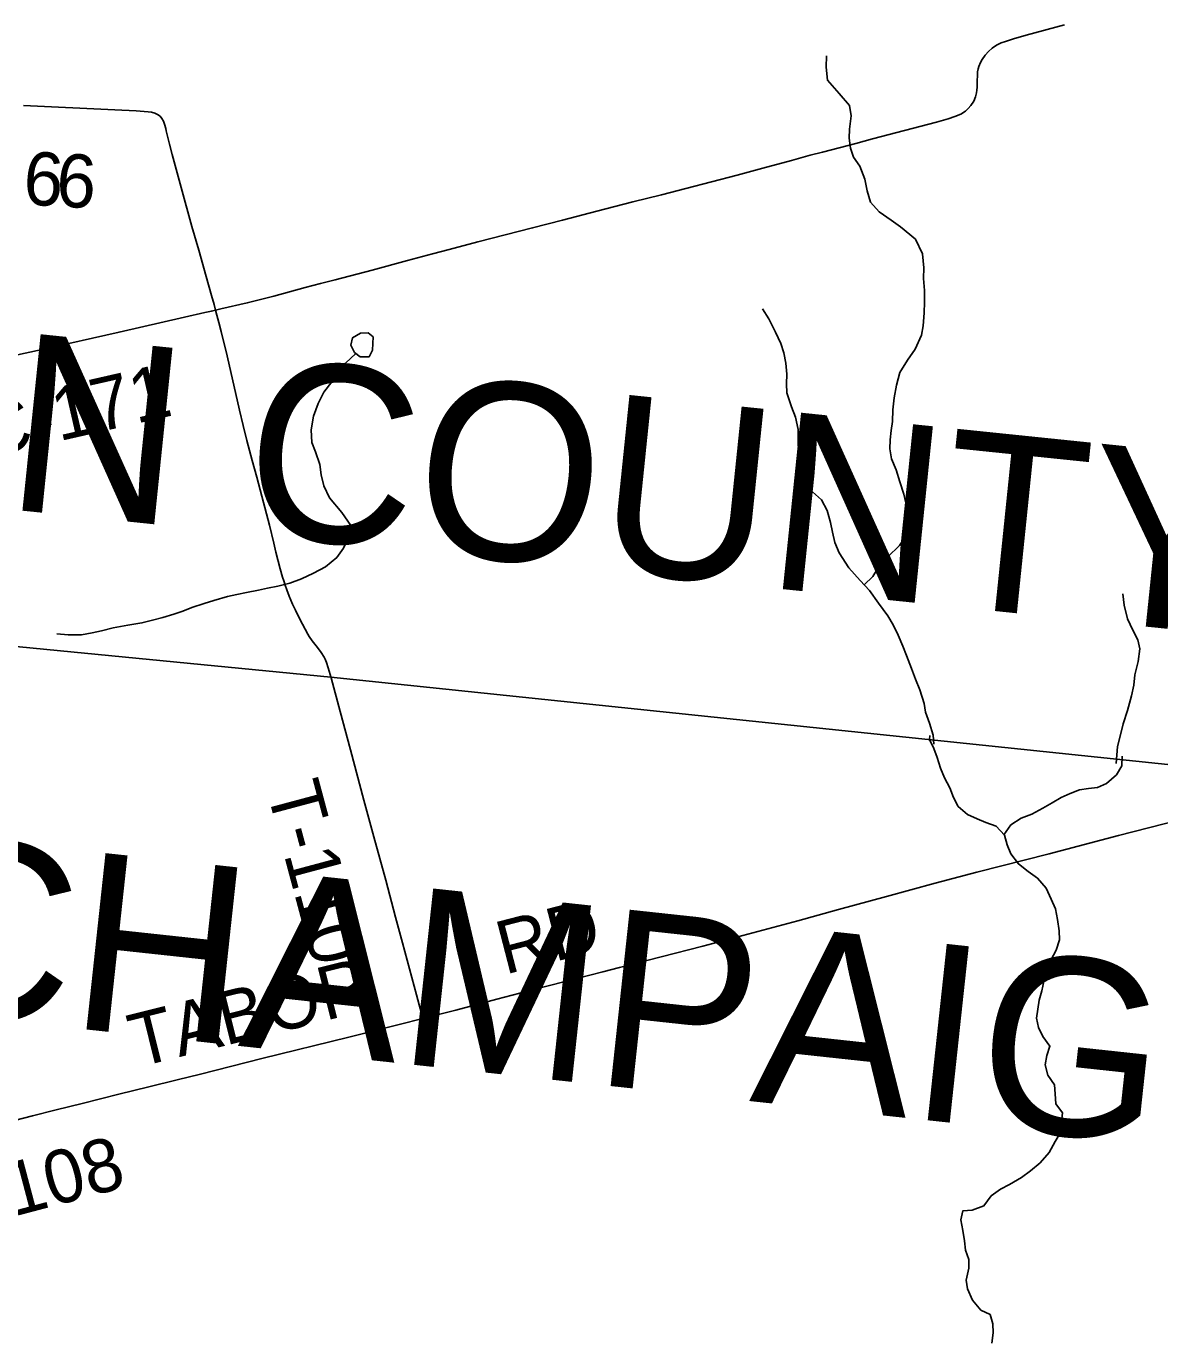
# Model space of a CAD drawing. Extents: x 0 to 1101, y 0 to 440.
# Drawn here: x 844.169 to 845.379, y 375.861 to 377.265 of the extents above; entities that cross this region are included whole.
import ezdxf

# ---------------------------------------------------------------- set-up
doc = ezdxf.new("R2010")
doc.units = 0
for name, color, linetype in [('GM_X_County_Road', 7, 'Continuous'), ('GM_X_County_Road_Text', 7, 'Continuous'), ('GM_X_County_Text', 7, 'Continuous'), ('GM_X_Minor_Lake', 7, 'Continuous'), ('GM_X_Minor_River', 7, 'Continuous'), ('GM_X_Township', 7, 'Continuous'), ('GM_X_Township_Road', 7, 'Continuous'), ('GM_X_Township_Road_Text', 7, 'Continuous'), ('SH_Cut_Line', 7, 'Continuous')]:
    doc.layers.add(name, color=color, linetype=linetype)

msp = doc.modelspace()

# ---------------------------------------------------------------- linework, layer by layer
at = {"layer": 'GM_X_County_Road'}
for points in [[(843.7743, 376.6401), (844.4941, 376.5699), (845.4182, 376.4736), (845.5612, 376.461), (845.6523, 376.4464), (845.8289, 376.4273), (846.6778, 376.3437), (847.4662, 376.2566), (847.5303, 377.0082), (847.5335, 377.0456), (847.6089, 377.9284)], [(844.1415, 376.9102), (844.186, 376.9197), (844.268, 376.9384), (844.3378, 376.9543), (844.3595, 376.9592), (844.3666, 376.9608), (844.371, 376.9617), (844.3766, 376.9631), (844.4048, 376.9696), (844.4333, 376.9766), (844.4668, 376.9859), (844.483, 376.9902), (844.4986, 376.9942), (844.5382, 377.0046), (844.576, 377.0148), (844.6024, 377.0219), (844.6204, 377.0267), (844.651, 377.0347), (844.7094, 377.0496), (844.7413, 377.0579), (844.7779, 377.0674), (844.8164, 377.0774), (844.8471, 377.0851), (844.873, 377.0917), (844.9278, 377.1058), (844.9553, 377.1133), (844.9859, 377.1217), (845.0056, 377.1272), (845.0188, 377.1306), (845.0544, 377.1399), (845.0722, 377.1449), (845.1405, 377.1627), (845.1531, 377.166), (845.1602, 377.1685), (845.1664, 377.1712), (845.1714, 377.1742), (845.1743, 377.177), (845.1774, 377.1802), (845.1805, 377.1851), (845.1822, 377.1896), (845.1834, 377.1938), (845.1838, 377.1966), (845.1839, 377.1999), (845.1841, 377.2041), (845.1839, 377.2073), (845.1842, 377.2116), (845.1845, 377.2161), (845.1851, 377.2194), (845.1859, 377.2221), (845.1874, 377.2262), (845.1893, 377.2294), (845.1924, 377.2339), (845.196, 377.238), (845.2001, 377.2416), (845.2046, 377.2447), (845.2095, 377.2473), (845.2144, 377.2488), (845.2227, 377.2514), (845.2363, 377.2555), (845.2772, 377.2665)], [(844.5922, 376.2055), (844.6274, 376.2145), (844.6713, 376.2262), (844.7122, 376.2368), (844.7428, 376.2448), (844.7843, 376.2555), (844.8023, 376.2601), (844.8911, 376.2827), (844.9924, 376.31), (845.036, 376.3221), (845.0871, 376.3359), (845.1392, 376.3502), (845.1835, 376.3617), (845.2609, 376.3815), (845.335, 376.4008), (845.3837, 376.4134), (845.4274, 376.4244)], [(844.0063, 376.0564), (844.0507, 376.0684), (844.1098, 376.0843), (844.1565, 376.0968), (844.1757, 376.1016), (844.201, 376.108), (844.2287, 376.115), (844.2679, 376.1247), (844.2999, 376.1326), (844.33, 376.14), (844.3548, 376.1462), (844.4204, 376.1628), (844.5133, 376.1858), (844.5669, 376.1991), (844.5922, 376.2055)]]:
    msp.add_lwpolyline(points, dxfattribs=at)
at = {"layer": 'GM_X_Minor_Lake'}
for points in [[(844.5253, 376.9121), (844.5348, 376.9119), (844.5384, 376.9191), (844.5394, 376.9332), (844.5338, 376.9375), (844.5258, 376.9372), (844.5173, 376.9324), (844.5153, 376.9244), (844.5193, 376.9167)], [(844.5193, 376.9167), (844.5253, 376.9121)]]:
    msp.add_lwpolyline(points, dxfattribs=at)
at = {"layer": 'GM_X_Minor_River'}
for points in [[(845.0635, 376.6685), (845.0728, 376.6775), (845.0787, 376.6874), (845.0885, 376.6986), (845.1012, 376.7106), (845.1099, 376.7238), (845.1102, 376.7394), (845.1089, 376.7516), (845.1057, 376.7654), (845.1014, 376.7784), (845.0975, 376.7914), (845.0924, 376.803), (845.0907, 376.8137), (845.0912, 376.8232), (845.0922, 376.8334), (845.0935, 376.8429), (845.0941, 376.8555), (845.0955, 376.8681), (845.098, 376.8817), (845.1013, 376.8954), (845.1096, 376.9086), (845.1178, 376.9202), (845.1246, 376.935), (845.1263, 376.9452), (845.1273, 376.9589), (845.1279, 376.9704), (845.1278, 376.9829), (845.1268, 376.9955), (845.1271, 377.007), (845.1255, 377.0219), (845.1181, 377.0376), (845.102, 377.0509), (845.0923, 377.0579), (845.0795, 377.0669), (845.0702, 377.077), (845.0666, 377.0892), (845.0642, 377.1018), (845.0588, 377.1157), (845.0521, 377.1253), (845.0489, 377.1349), (845.0472, 377.1456), (845.0477, 377.1551), (845.0495, 377.1692), (845.0478, 377.1803), (845.0366, 377.193), (845.0244, 377.2074), (845.0227, 377.2211), (845.023, 377.2333)], [(845.1379, 376.4985), (845.1369, 376.508), (845.133, 376.521), (845.129, 376.5325), (845.1273, 376.542), (845.1227, 376.5566), (845.1183, 376.5677), (845.114, 376.5793), (845.1085, 376.5931), (845.1045, 376.6031), (845.0998, 376.6149), (845.0943, 376.6257), (845.0888, 376.6353), (845.0788, 376.6489), (845.0691, 376.6624), (845.0591, 376.6732), (845.0471, 376.6868), (845.0368, 376.7026), (845.0321, 376.7137), (845.0296, 376.7248), (845.0275, 376.7351), (845.024, 376.7478), (845.0177, 376.7593), (845.005, 376.7706), (844.9991, 376.7814), (844.9941, 376.796), (844.9932, 376.8105), (844.993, 376.8223), (844.9929, 376.8345), (844.9901, 376.8475), (844.9857, 376.8586), (844.9807, 376.8736), (844.9805, 376.8831), (844.9807, 376.8934), (844.9798, 376.9052), (844.9777, 376.9163), (844.9745, 376.9263), (844.9686, 376.9382), (844.9617, 376.9524), (844.955, 376.9632)], [(844.2016, 376.6163), (844.2138, 376.6153), (844.2278, 376.6151), (844.2393, 376.6175), (844.2492, 376.6193), (844.2618, 376.6225), (844.2775, 376.6256), (844.2924, 376.628), (844.3038, 376.6309), (844.3146, 376.6338), (844.3264, 376.6374), (844.336, 376.6406), (844.3456, 376.6443), (844.359, 376.6486), (844.3693, 376.6519), (844.3838, 376.6562), (844.3938, 376.6583), (844.4041, 376.6604), (844.4167, 376.6628), (844.4266, 376.665), (844.4373, 376.6671), (844.4503, 376.6703), (844.4629, 376.675), (844.4756, 376.6809), (844.4883, 376.6879), (844.5003, 376.6976), (844.5077, 376.7078), (844.5133, 376.7198), (844.5154, 376.732), (844.5058, 376.7459), (844.4927, 376.7614), (844.4865, 376.7744), (844.4837, 376.7859), (844.4824, 376.797), (844.4777, 376.8104), (844.4737, 376.8204), (844.4732, 376.8341), (844.4754, 376.8485), (844.4806, 376.8622), (844.4865, 376.8743), (844.4951, 376.8852), (844.5025, 376.8953), (844.5096, 376.9051), (844.5208, 376.9156)], [(845.3324, 376.4779), (845.3338, 376.496), (845.3367, 376.507), (845.34, 376.5203), (845.3444, 376.5343), (845.3489, 376.5502), (845.3514, 376.5616), (845.3524, 376.5726), (845.3557, 376.5867), (845.3575, 376.6004), (845.3554, 376.6099), (845.3503, 376.6203), (845.3444, 376.6322), (845.3409, 376.6468), (845.3396, 376.659)], [(845.1638, 376.4319), (845.1586, 376.4415), (845.1549, 376.4518), (845.1492, 376.4626), (845.1448, 376.4729), (845.1414, 376.4844), (845.1377, 376.4939), (845.1332, 376.5035), (845.1333, 376.5077)], [(845.2126, 376.4018), (845.22, 376.4123), (845.2311, 376.4195), (845.2422, 376.4236), (845.254, 376.43), (845.264, 376.436), (845.2736, 376.4416), (845.2831, 376.4457), (845.2934, 376.4498), (845.303, 376.4512), (845.3125, 376.4523), (845.322, 376.4564), (845.3328, 376.4658), (845.3386, 376.4753), (845.3387, 376.4856)], [(845.1998, 375.859), (845.2011, 375.87), (845.2008, 375.8796), (845.1978, 375.8895), (845.188, 375.8942), (845.1789, 375.9049), (845.1737, 375.9168), (845.1723, 375.9263), (845.175, 375.9389), (845.1751, 375.9484), (845.1714, 375.9584), (845.1704, 375.9683), (845.1686, 375.9794), (845.1664, 375.9908), (845.1687, 376.0003), (845.1786, 376.001), (845.1912, 376.0055), (845.199, 376.0161), (845.2089, 376.0232), (845.2185, 376.0285), (845.2315, 376.036), (845.2411, 376.0431), (845.2511, 376.0514), (845.261, 376.0624), (845.2672, 376.0741), (845.2742, 376.0855), (845.2739, 376.095), (845.2751, 376.105), (845.268, 376.1145), (845.2673, 376.1252), (845.2666, 376.1348), (845.2595, 376.1451), (845.2566, 376.1562), (845.2582, 376.1661), (845.2617, 376.176), (845.2542, 376.1863), (845.2493, 376.1959), (845.2475, 376.2058), (845.2487, 376.2157), (845.2503, 376.2253), (845.2531, 376.2352), (845.2551, 376.245), (845.2582, 376.2565), (845.2625, 376.2679), (845.2683, 376.2785), (845.2718, 376.2895), (845.2715, 376.299), (845.2697, 376.3112), (845.2675, 376.3227), (845.2631, 376.333), (845.2575, 376.3449), (845.2484, 376.3553), (845.2386, 376.3626), (845.228, 376.3707), (845.2201, 376.3815), (845.216, 376.391), (845.213, 376.4014), (845.2044, 376.411), (845.1934, 376.4149), (845.1839, 376.4188), (845.1736, 376.4234), (845.1638, 376.4319)]]:
    msp.add_lwpolyline(points, dxfattribs=at)
at = {"layer": 'GM_X_Township'}
msp.add_lwpolyline([(843.7743, 376.6401), (844.4941, 376.5699), (845.4182, 376.4736), (845.5612, 376.461), (845.6523, 376.4464), (845.649, 376.3795), (845.6323, 376.2442), (845.56, 375.6723), (845.4198, 374.5609), (845.4081, 374.4677), (845.355, 374.0482), (845.2, 372.8166), (844.9343, 370.7914), (844.8107, 369.7452), (844.7764, 369.459), (844.7671, 369.3901), (844.6729, 368.4734), (843.0244, 368.6428)], dxfattribs=at)
at = {"layer": 'GM_X_Township_Road'}
for points in [[(844.371, 376.9617), (844.3695, 376.9678), (844.3668, 376.9775), (844.3611, 376.9978), (844.3531, 377.0258), (844.3458, 377.051), (844.3344, 377.0928), (844.3247, 377.1281), (844.3217, 377.139), (844.3184, 377.1531), (844.3178, 377.1559), (844.3165, 377.1604), (844.3153, 377.1637), (844.3138, 377.1664), (844.3117, 377.1689), (844.309, 377.1708), (844.3062, 377.1722), (844.3026, 377.1732), (844.2991, 377.1737), (844.2863, 377.1747), (844.2634, 377.1758), (844.1659, 377.1804)], [(844.4943, 376.5693), (844.4912, 376.5801), (844.4894, 376.5857), (844.488, 376.5892), (844.4869, 376.5914), (844.4838, 376.5964), (844.4797, 376.6017), (844.4741, 376.6088), (844.471, 376.6133), (844.4694, 376.6158), (844.461, 376.632), (844.4562, 376.6417), (844.4533, 376.6478), (844.4496, 376.6563), (844.447, 376.6631), (844.4452, 376.6681), (844.4437, 376.673), (844.4426, 376.6769), (844.4401, 376.6855), (844.4354, 376.7035), (844.4331, 376.7131), (844.4284, 376.7322), (844.4253, 376.7442), (844.4204, 376.7633), (844.4149, 376.7835), (844.4099, 376.8014), (844.4042, 376.8225), (844.4004, 376.8387), (844.3965, 376.855), (844.3833, 376.9131), (844.3769, 376.9391), (844.3745, 376.9487), (844.3725, 376.9564), (844.371, 376.9617)], [(844.5922, 376.2055), (844.5855, 376.231), (844.5707, 376.2862), (844.5631, 376.3138), (844.5526, 376.3534), (844.5399, 376.3995), (844.5294, 376.4385), (844.5149, 376.4925), (844.504, 376.5333), (844.4943, 376.5693)]]:
    msp.add_lwpolyline(points, dxfattribs=at)
at = {"layer": 'SH_Cut_Line'}
for points in [[(843.7743, 376.6401), (844.4941, 376.5699), (845.4182, 376.4736), (845.5612, 376.461), (845.6523, 376.4464), (845.8289, 376.4273), (846.6778, 376.3437), (847.4662, 376.2566), (847.7946, 376.221), (849.0627, 376.0925), (849.9034, 375.9956), (850.1463, 375.9688), (850.9258, 375.8797), (850.9258, 381.9059), (837.3258, 381.9059)], [(837.3258, 368.3059), (850.9258, 368.3059), (850.9258, 375.8797), (850.1463, 375.9688), (849.9034, 375.9956), (849.0627, 376.0925), (847.7946, 376.221), (847.4662, 376.2566), (846.6778, 376.3437), (845.8289, 376.4273), (845.6523, 376.4464), (845.5612, 376.461), (845.4182, 376.4736), (844.4941, 376.5699), (843.7743, 376.6401)]]:
    msp.add_lwpolyline(points, dxfattribs=at)

# ---------------------------------------------------------------- texts
at = {"layer": 'GM_X_County_Road_Text'}
for s, rotation, p in [('C-171', 12.829, (844.1254, 376.8039)), ('RD', 14.5196, (844.6797, 376.2522)), ('TABOR', 13.9889, (844.2871, 376.153)), ('C-108', 14.8275, (844.0774, 375.9733))]:
    msp.add_text(s, height=0.05682, rotation=rotation, dxfattribs=at).set_placement(p)
at = {"layer": 'GM_X_County_Text'}
for s, rotation, p in [('LOGAN COUNTY', 354.1087, (843.4441, 376.8221)), ('CHAMPAIGN COUNTY', 353.8398, (844.0307, 376.2157))]:
    msp.add_text(s, height=0.189394, rotation=rotation, dxfattribs=at).set_placement(p)
at = {"layer": 'GM_X_Township_Road_Text'}
for s, height, rotation, p in [('6', 0.0568, 356.5359, (844.1647, 377.0749)), ('6', 0.0568, 356.548, (844.1997, 377.0728)), ('T-110', 0.05682, 284.9902, (844.4251, 376.4504))]:
    msp.add_text(s, height=height, rotation=rotation, dxfattribs=at).set_placement(p)

doc.saveas('drawing.dxf')
